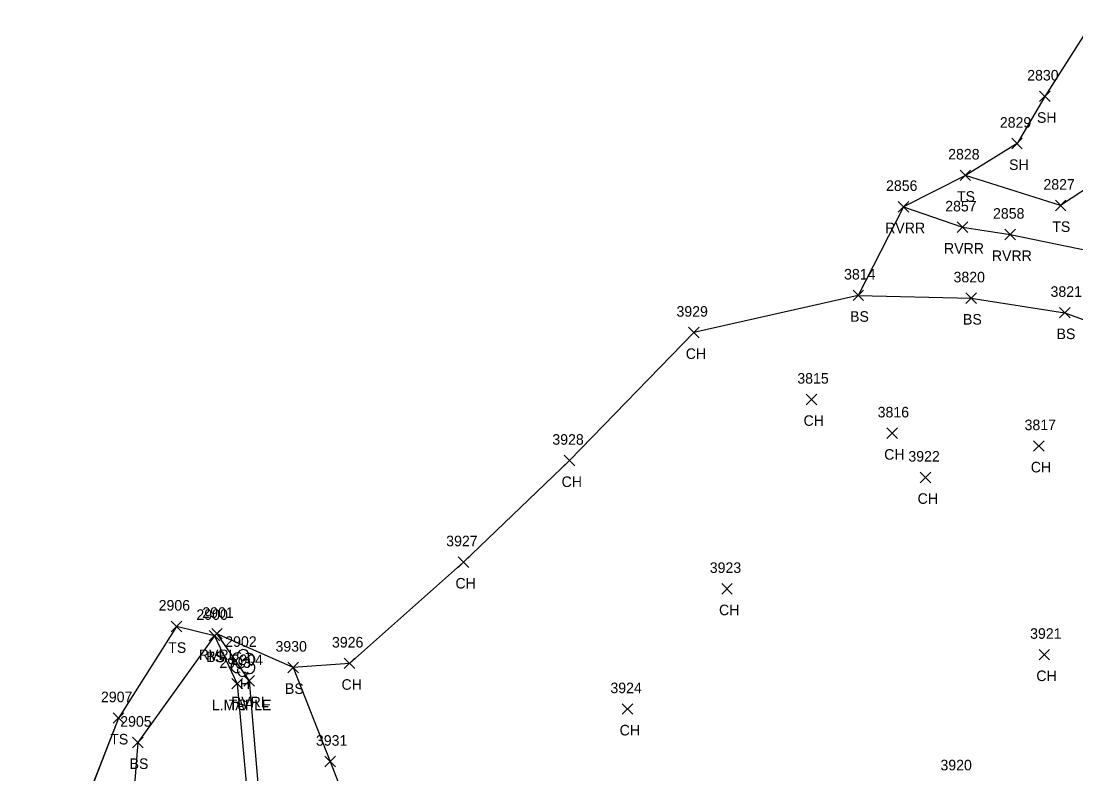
# Model space of a CAD drawing. Extents: x 1443590 to 1445966, y 578314 to 580556.
# Drawn here: x 1444095.7 to 1444295.6, y 579065.6 to 579208.1 of the extents above; entities that cross this region are included whole.
import ezdxf

# ---------------------------------------------------------------- set-up
doc = ezdxf.new("R2010")
doc.units = 0
for name, color, linetype in [('L_A', 7, 'Continuous'), ('L_C', 7, 'Continuous'), ('L_I', 7, 'Continuous'), ('L_TIC', 7, 'Continuous'), ('LAWE', 7, 'Continuous'), ('LELB', 7, 'Continuous'), ('LSOGP', 7, 'Continuous'), ('LTD', 7, 'Continuous')]:
    doc.layers.add(name, color=color, linetype=linetype)

msp = doc.modelspace()

# ---------------------------------------------------------------- linework, layer by layer
at = {"layer": 'L_TIC'}
for points in [[(1444288.74, 579192.87), (1444290.74, 579194.87)], [(1444290.74, 579192.87), (1444288.74, 579194.87)], [(1444283.46, 579183.94), (1444285.46, 579185.94)], [(1444285.46, 579183.94), (1444283.46, 579185.94)], [(1444273.67, 579177.92), (1444275.67, 579179.92)], [(1444275.67, 579177.92), (1444273.67, 579179.92)], [(1444261.96, 579171.97), (1444263.96, 579173.97)], [(1444263.96, 579171.97), (1444261.96, 579173.97)], [(1444291.72, 579172.21), (1444293.72, 579174.21)], [(1444293.72, 579172.21), (1444291.72, 579174.21)], [(1444273.11, 579168.09), (1444275.11, 579170.09)], [(1444275.11, 579168.09), (1444273.11, 579170.09)], [(1444282.17, 579166.71), (1444284.17, 579168.71)], [(1444284.17, 579166.71), (1444282.17, 579168.71)], [(1444253.38, 579155.2), (1444255.38, 579157.2)], [(1444255.38, 579155.2), (1444253.38, 579157.2)], [(1444274.78, 579154.66), (1444276.78, 579156.66)], [(1444276.78, 579154.66), (1444274.78, 579156.66)], [(1444292.5, 579151.92), (1444294.5, 579153.92)], [(1444294.5, 579151.92), (1444292.5, 579153.92)], [(1444222.2, 579148.16), (1444224.2, 579150.16)], [(1444224.2, 579148.16), (1444222.2, 579150.16)], [(1444244.52, 579135.49), (1444246.52, 579137.49)], [(1444246.52, 579135.49), (1444244.52, 579137.49)], [(1444259.8, 579129.09), (1444261.8, 579131.09)], [(1444261.8, 579129.09), (1444259.8, 579131.09)], [(1444287.58, 579126.68), (1444289.58, 579128.68)], [(1444289.58, 579126.68), (1444287.58, 579128.68)], [(1444198.67, 579123.92), (1444200.67, 579125.92)], [(1444200.67, 579123.92), (1444198.67, 579125.92)], [(1444266.13, 579120.73), (1444268.13, 579122.73)], [(1444268.13, 579120.73), (1444266.13, 579122.73)], [(1444178.56, 579104.7), (1444180.56, 579106.7)], [(1444180.56, 579104.7), (1444178.56, 579106.7)], [(1444228.5, 579099.65), (1444230.5, 579101.65)], [(1444230.5, 579099.65), (1444228.5, 579101.65)], [(1444124.21, 579092.52), (1444126.21, 579094.52)], [(1444126.21, 579092.52), (1444124.21, 579094.52)], [(1444131.4, 579090.77), (1444133.4, 579092.77)], [(1444133.4, 579090.77), (1444131.4, 579092.77)], [(1444131.4, 579090.77), (1444133.4, 579092.77)], [(1444133.4, 579090.77), (1444131.4, 579092.77)], [(1444131.86, 579091.15), (1444133.86, 579093.15)], [(1444133.86, 579091.15), (1444131.86, 579093.15)], [(1444288.63, 579087.18), (1444290.63, 579089.18)], [(1444290.63, 579087.18), (1444288.63, 579089.18)], [(1444146.3, 579084.75), (1444148.3, 579086.75)], [(1444148.3, 579084.75), (1444146.3, 579086.75)], [(1444156.97, 579085.53), (1444158.97, 579087.53)], [(1444158.97, 579085.53), (1444156.97, 579087.53)], [(1444137.96, 579082.21), (1444139.96, 579084.21)], [(1444139.96, 579082.21), (1444137.96, 579084.21)], [(1444135.67, 579081.68), (1444137.67, 579083.68)], [(1444137.67, 579081.68), (1444135.67, 579083.68)], [(1444209.67, 579076.89), (1444211.67, 579078.89)], [(1444211.67, 579076.89), (1444209.67, 579078.89)], [(1444113.22, 579075.18), (1444115.22, 579077.18)], [(1444115.22, 579075.18), (1444113.22, 579077.18)], [(1444116.87, 579070.54), (1444118.87, 579072.54)], [(1444118.87, 579070.54), (1444116.87, 579072.54)], [(1444153.3, 579066.94), (1444155.3, 579068.94)], [(1444155.3, 579066.94), (1444153.3, 579068.94)]]:
    msp.add_lwpolyline(points, dxfattribs=at)
at = {"layer": 'LAWE'}
for points in [[(1444262.96, 579172.97), (1444274.11, 579169.09), (1444283.17, 579167.71), (1444300.31, 579164.19), (1444309.37, 579162.67), (1444332.16, 579152.06), (1444345.18, 579142.09), (1444354.88, 579132.23), (1444360.95, 579125.41), (1444366.81, 579116.47), (1444365.27, 579103.46), (1444363.21, 579091.32), (1444369.15, 579079.68), (1444366.13, 579066.94), (1444369.44, 579051.85), (1444379.35, 579035.17), (1444388.22, 579024.4)], [(1444132.86, 579092.15), (1444138.96, 579083.21), (1444141.19, 579057.08), (1444148.07, 579045.28), (1444167.25, 579025.02), (1444174.77, 579019.56), (1444188.42, 579002.67), (1444202.86, 578984.81), (1444211.08, 578975.97), (1444218.07, 578968.05), (1444223.32, 578965.93), (1444225.77, 578959.78), (1444234.82, 578940.52), (1444239.56, 578925.63), (1444236.72, 578915.57)]]:
    msp.add_lwpolyline(points, dxfattribs=at)
at = {"layer": 'LELB'}
for points in [[(1444546.27, 579164.71), (1444527.41, 579165.01), (1444518.68, 579164.58), (1444494.24, 579168.63), (1444454.42, 579172.45), (1444423.27, 579178.31), (1444391.3, 579180.61), (1444354.48, 579186.56), (1444320.83, 579190.46), (1444308.41, 579190.29), (1444300.6, 579178.38), (1444292.72, 579173.21), (1444274.67, 579178.92)], [(1444254.38, 579156.2), (1444275.78, 579155.66), (1444293.5, 579152.92), (1444307.24, 579147.91), (1444320.81, 579127.52), (1444330.34, 579110.26), (1444346.59, 579090.69), (1444355.59, 579073.52), (1444357.14, 579058.92), (1444358.82, 579047.8), (1444374.51, 579024.23)], [(1444125.21, 579093.52), (1444114.22, 579076.18), (1444106.46, 579056.3), (1444102.71, 579032.42), (1444096.14, 579003.38), (1444095.75, 578980.58), (1444103.11, 578980.1), (1444109.24, 578962.26), (1444131.97, 578946.27)], [(1444132.4, 579091.77), (1444117.87, 579071.54), (1444116.09, 579049.13), (1444110.26, 579032.25), (1444101.83, 578997.66), (1444107.85, 578981.96), (1444112.46, 578966.04), (1444127.21, 578969.33)], [(1444132.4, 579091.77), (1444136.67, 579082.68), (1444139.09, 579056.28), (1444146.23, 579043.3), (1444162.39, 579025.62), (1444164.59, 579023.19)], [(1444147.3, 579085.75), (1444154.3, 579067.94), (1444160.7, 579051.51), (1444170.69, 579032.78), (1444198.19, 579008.64), (1444217.42, 578989.47)]]:
    msp.add_lwpolyline(points, dxfattribs=at)
at = {"layer": 'LSOGP'}
msp.add_lwpolyline([(1444298.83, 579208.12), (1444289.74, 579193.87), (1444284.47, 579184.93), (1444274.68, 579178.92), (1444262.97, 579172.96), (1444254.38, 579156.2), (1444223.2, 579149.16), (1444199.68, 579124.92), (1444179.57, 579105.7), (1444157.97, 579086.53), (1444147.3, 579085.75), (1444132.86, 579092.15), (1444132.4, 579091.76), (1444125.21, 579093.52), (1444114.22, 579076.18), (1444106.47, 579056.3)], dxfattribs=at)
at = {"layer": 'LTD'}
msp.add_line((1444137.77, 579086.66), (1444137.77, 579086.66), dxfattribs=at)
msp.add_line((1444137.77, 579086.66), (1444137.77, 579086.66), dxfattribs=at)
msp.add_arc((1444137.82, 579088.09), 1.05, 335.5272, 180.9563, dxfattribs=at)
for centre, major_axis, ratio, start_param, end_param in [((1444136.98, 579087.33), (1.21, -0.51), 0.895232, 1.570796, 4.712389), ((1444138.81, 579087.24), (-1.14, -0.48), 0.949671, 1.570796, 4.712389), ((1444136.69, 579085.95), (0.58, -1.04), 0.959034, 3.141593, 6.283185), ((1444137.56, 579087.12), (-0.208, -0.792), 0.645439, 3.141593, 6.283185), ((1444138.27, 579086.49), (-0.5, 0.667), 0.989748, 3.141593, 6.283185), ((1444138.77, 579085.83), (-1.09, 0.79), 0.841452, 1.570796, 4.712389), ((1444137.77, 579085.16), (0.26, 1.06), 0.942809, 1.570796, 4.712389), ((1444137.31, 579085.91), (-0.625, -0.083), 0.423636, 0, 3.141593)]:
    msp.add_ellipse(centre, major_axis=major_axis, ratio=ratio, start_param=start_param, end_param=end_param, dxfattribs=at)

# ---------------------------------------------------------------- texts
at = {"layer": 'L_A'}
for s, p in [('SH', (1444288.23, 579188.87)), ('SH', (1444282.95, 579179.94)), ('TS', (1444273.08, 579173.92)), ('RVRR', (1444259.47, 579167.97)), ('TS', (1444291.13, 579168.21)), ('RVRR', (1444270.62, 579164.09)), ('RVRR', (1444279.69, 579162.71)), ('BS', (1444252.82, 579151.2)), ('BS', (1444274.22, 579150.66)), ('BS', (1444291.94, 579147.92)), ('CH', (1444221.69, 579144.16)), ('CH', (1444244.01, 579131.49)), ('CH', (1444259.29, 579125.09)), ('CH', (1444287.07, 579122.68)), ('CH', (1444198.16, 579119.92)), ('CH', (1444265.62, 579116.73)), ('CH', (1444178.05, 579100.7)), ('CH', (1444227.99, 579095.65)), ('TS', (1444123.62, 579088.52)), ('RVRL', (1444129.43, 579087.15)), ('TS', (1444130.81, 579086.77)), ('BS', (1444130.84, 579086.77)), ('CH', (1444288.12, 579083.18)), ('H', (1444137.2, 579081.66)), ('BS', (1444145.74, 579080.75)), ('CH', (1444156.46, 579081.53)), ('RVRL', (1444135.53, 579078.21)), ('TS', (1444135.08, 579077.68)), ('CH', (1444209.16, 579072.89)), ('TS', (1444112.63, 579071.18)), ('BS', (1444116.31, 579066.54))]:
    msp.add_text(s, height=2, dxfattribs=at).set_placement(p)
at = {"layer": 'L_C'}
msp.add_text('L.MAPLE', height=2, dxfattribs=at).set_placement((1444131.88, 579077.66))
at = {"layer": 'L_I'}
for s, p in [('2830', (1444286.39, 579196.87)), ('2829', (1444281.2, 579187.94)), ('2828', (1444271.41, 579181.92)), ('2856', (1444259.64, 579175.97)), ('2827', (1444289.46, 579176.21)), ('2857', (1444270.85, 579172.09)), ('2858', (1444279.91, 579170.71)), ('3814', (1444251.69, 579159.2)), ('3820', (1444272.43, 579158.66)), ('3821', (1444290.81, 579155.92)), ('3929', (1444219.93, 579152.16)), ('3815', (1444242.83, 579139.49)), ('3816', (1444258.05, 579133.09)), ('3817', (1444285.89, 579130.68)), ('3928', (1444196.41, 579127.92)), ('3922', (1444263.87, 579124.73)), ('3927', (1444176.3, 579108.7)), ('3923', (1444226.24, 579103.65)), ('2906', (1444121.81, 579096.52)), ('2900', (1444128.97, 579094.77)), ('2900', (1444128.97, 579094.77)), ('2901', (1444130.09, 579095.15)), ('3921', (1444286.94, 579091.18)), ('2902', (1444134.43, 579089.66)), ('3930', (1444143.95, 579088.75)), ('3926', (1444154.65, 579089.53)), ('2904', (1444135.62, 579086.21)), ('2903', (1444133.33, 579085.68)), ('3924', (1444207.41, 579080.89)), ('2907', (1444110.88, 579079.18)), ('2905', (1444114.53, 579074.54)), ('3931', (1444151.61, 579070.94)), ('3920', (1444269.95, 579066.28))]:
    msp.add_text(s, height=2, dxfattribs=at).set_placement(p)

doc.saveas('drawing.dxf')
